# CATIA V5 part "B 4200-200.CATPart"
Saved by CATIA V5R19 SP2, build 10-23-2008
Part number: B 4200-200
Bounding box of the stored display mesh (mm): x -47.487 to 47.487, y -47.487 to 47.487, z 0 to 520
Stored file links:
  C:\Users\Bora\Desktop\3D Katı model\B serisi\B 4200\B 4200-200.CATPart
  C:\Program Files\Dassault Systemes\B19\intel_a\reffiles\standard\MetricThickPitch.txt
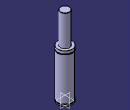
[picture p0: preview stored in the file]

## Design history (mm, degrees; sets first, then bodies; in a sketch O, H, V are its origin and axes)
Body1 (main body)
  Sketch1 on yz-plane, origin (0, 0, 0), H (0, 1, 0), V (0, 0, 1)
    point P1 (47.5, 298.5)
    point P2 (47.5, 293.5)
    point P3 (47.5, 298.5)
    point P6 (47.5, 293.5)
    point P9 (30, 519)
    point P11 (30, 519)
    arc A1 centre (47.5, 296) radius 2.5 from (47.5, 298.5) to (47.5, 293.5) ccw
    line L1 (47.5, 298.5) -> (47.5, 317)
    line L2 (47.5, 13) -> (47.5, 293.5)
    line L3 (43.5, 13) -> (43.5, 8)
    arc A2 centre (29, 519) radius 1 from (30, 519) to (29, 520) ccw
    line L4 (30, 519) -> (30, 317)
    line L5 (47.5, 0) -> (47.5, 8)
    line L6 (29, 520) -> (0, 520)
    point P15 (0, 520)
    line L7 (30, 317) -> (47.5, 317)
    line L8 (0, 0) -> (47.5, 0)
    line L9 (43.5, 13) -> (47.5, 13)
    line L10 (43.5, 8) -> (47.5, 8)
    coincidence: P15 V, P1 P3, P2 P6, P9 P11
    tangency: L6 A2
    horizontal: L7 H, L8 H, L9 H, L10 H
  Shaft1: profile Sketch1, axis Sketch1.V, angle 360
  Sketch2 on face of Shaft1 from Sketch1.L8, origin (0, 0, 0), H (1, 0, 0), V (0, -1, 0)
    point P1 (30, 0)
    distance P1 V = 30
  Hole1: placed by Sketch2, at (30, 0, 0) direction (0, 0, 1), diameter 6.647, depth 13, threaded "M8", thread diameter 8, thread depth 13, pitch 1.25
  CircPattern1: of Hole1, instances 4, angular step 90, axis from xy-plane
